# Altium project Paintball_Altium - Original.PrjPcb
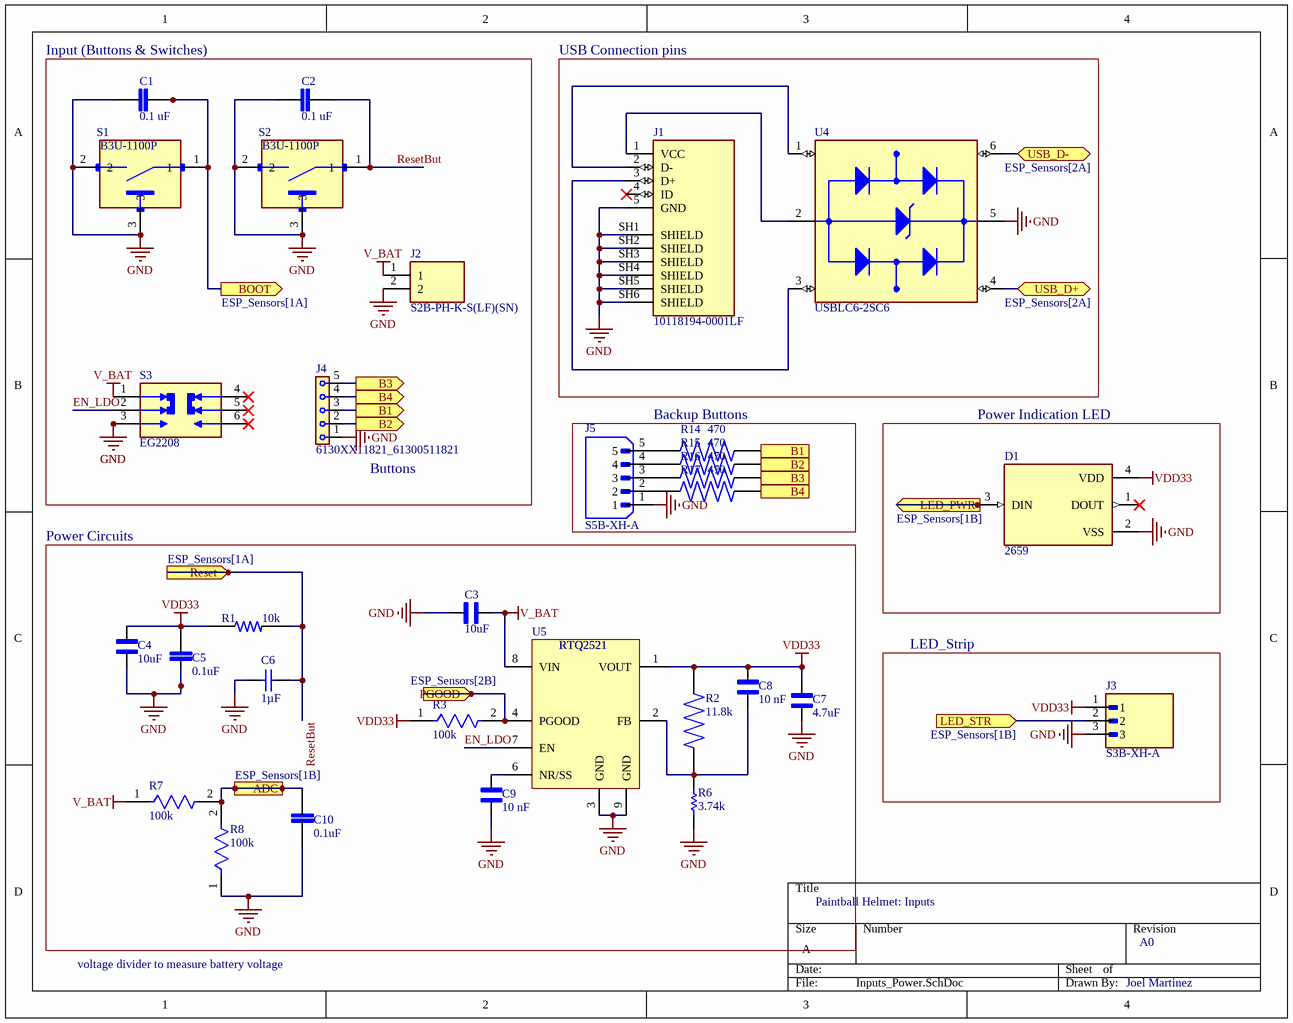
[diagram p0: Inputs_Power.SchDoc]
2 sheets, 55 parts. Net scope: flat (ports and power ports of the same name join across sheets).
Board files: Paintball_PCB_copy.PcbDoc, Paintball_PCB.PcbDoc
Sheets:
  Inputs_Power.SchDoc
  ESP_Sensors.SchDoc

## Sheet Inputs_Power.SchDoc
size A; SheetNumber: 1; SheetTotal: 2

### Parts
C1  0.1 uF  [CAPC1608X90]
C2  0.1 uF  [CAPC1608X90]
C3  10uF  [CAPC1608X90N]
C4  10uF  [CAPC1608X90N]
C5  0.1uF  [CAPC1608X90]
C6  1µF  [CAPC1608X90X35LL15T15]
C7  4.7uF  [CAPC1608X95N]
C8  10 nF  [CAPC1608X90N]
C9  10 nF  [CAPC1608X90N]
C10  0.1uF  [CAPC1608X90]
D1  2659  [2659]
J1  10118194-0001LF  [AMPHENOL_10118194-0001LF]
J2  S2B-PH-K-S(LF)(SN)  [JST_S2B-PH-K-S(LF)(SN)]
J3  S3B-XH-A  [JST_S3B-XH-A]
J4  6130XX11821_61300511821  [61300511821]
J5  S5B-XH-A  [JST_S5B-XH-A]
R1  10k  [RESC1607X60N]
R2  11.8k  [RESC1508X55N]
R3  100k  [FP-RC0603-0_55-MFG]
R6  3.74k  [RESC1609X50X30LL10T20]
R7  100k  [FP-RC0603-0_55-MFG]
R8  100k  [FP-RC0603-0_55-MFG]
R14  470  [RESC1608X55N]
R15  470  [RESC1608X55N]
R16  470  [RESC1608X55N]
R17  470  [RESC1608X55N]
S1  B3U-1100P  [SW_B3U-1100P]
S2  B3U-1100P  [SW_B3U-1100P]
S3  EG2208  [SW_EG2208]
U4  USBLC6-2SC6  [SOT95P280X145-6N]
U5  RTQ2521  [RTQ2521]

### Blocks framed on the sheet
USB Connection pins: J1 U4
Backup Buttons: J5 R14-R17
Power Indication LED: D1
Power Circuits: C3-C10 R1-R3 R6-R8 U5
LED_Strip: J3

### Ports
ADC (in, see ESP_Sensors[1B]), B1 (out, see ESP_Sensors[1A], Inputs_Power[2B]), B1 (out, see ESP_Sensors[1A], Inputs_Power[3B]), B2 (out, see ESP_Sensors[1A], Inputs_Power[2B]), B2 (out, see ESP_Sensors[1A], Inputs_Power[3B]), B3 (out, see ESP_Sensors[1A], Inputs_Power[2B]), B3 (out, see ESP_Sensors[1A], Inputs_Power[3B]), B4 (out, see ESP_Sensors[1A], Inputs_Power[2B]), B4 (out, see ESP_Sensors[1A], Inputs_Power[3B]), BOOT (out, see ESP_Sensors[1A]), LED_PWR (in, see ESP_Sensors[1B]), LED_STR (in, see ESP_Sensors[1B]), PGOOD (out, see ESP_Sensors[2B]), Reset (out, see ESP_Sensors[1A]), USB_D+ (bidir, see ESP_Sensors[2A]), USB_D- (bidir, see ESP_Sensors[2A])

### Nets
GND: C1.1 C2.1 C3.1 C4.1 C5.1 C6.1 C7.1 C9.1 C10.1 D1.2(VSS) J1.5(GND) J1.SH1(SHIELD) J1.SH2(SHIELD) J1.SH3(SHIELD) J1.SH4(SHIELD) J1.SH5(SHIELD) J1.SH6(SHIELD) J2.2 J3.3 J4.1 J5.1 R6.1 R8.1 S1.2 S1.3 S2.2 S2.3 S3.3 U4.5(VBUS) U5.3(GND) U5.9(GND)
V_BAT: C3.2 J2.1 R7.1 S3.1 U5.8(VIN)
VDD33: C4.2 C5.2 C7.2 C8.2 D1.4(VDD) J3.1 R1.1 R2.2 R3.1 U5.1(VOUT)
B1: J4.3 R14.2 ; port B1
B2: J4.2 R15.2 ; port B2
B3: J4.5 R16.2 ; port B3
B4: J4.4 R17.2 ; port B4
EN_LDO: S3.2 U5.7(EN)
ResetBut: C2.2 C6.2 R1.2 S2.1 ; port Reset  [project net Reset]
NetC1_2: C1.2 S1.1 ; port BOOT
NetC8_1: C8.1 R2.1 R6.2 U5.2(FB)
NetC9_2: C9.2 U5.6(NR/SS)
NetC10_2: C10.2 R7.2 R8.2 ; port ADC
NetD1_3: D1.3(DIN) ; port LED_PWR
NetJ1_1: J1.1(VCC) U4.2(GND)
NetJ1_2: J1.2(D-) U4.1(I/O1_IN)
NetJ1_3: J1.3(D+) U4.3(I/O2_IN)
NetJ3_2: J3.2 ; port LED_STR
NetJ5_2: J5.2 R17.1
NetJ5_3: J5.3 R16.1
NetJ5_4: J5.4 R15.1
NetJ5_5: J5.5 R14.1
NetR3_2: R3.2 U5.4(PGOOD) ; port PGOOD
NetU4_4: U4.4(I/O2_OUT) ; port USB_D+
NetU4_6: U4.6(I/O1_OUT) ; port USB_D-

Not connected (* = marked no-connect by the designer): D1 1(DOUT)*; J1 4(ID)*; S3 4* 5* 6*

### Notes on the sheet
- (near C1) Input (Buttons & Switches)
- (near J4) Buttons
- Paintball Helmet: Inputs
- voltage divider to measure battery voltage
- A0
- Joel Martinez

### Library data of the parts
C1 C2 C5 C10 = C0603C104K5RACTU: 0.1 ÂµF Â±10% 50V Ceramic Capacitor X7R 0603 (1608 Metric); MF: KEMET
C3 C4 = CL10A106KP8NNNC: 10 ÂµF Â±10% 10V Ceramic Capacitor X5R 0603 (1608 Metric); MF: Samsung
C6 = CMP-2006-02241-1: Part Number: C0603C105K9PACTU; Manufacturer: Kemet
C7 = CL10B475KQ8NQNC: 4.7 ÂµF Â±10% 6.3V Ceramic Capacitor X7R 0603 (1608 Metric); MF: Samsung Electro-Mechanics
C8 C9 = C0603C103K5RACTU: 10000 pF ±10% 50V Ceramic Capacitor X7R 0603 (1608 Metric)
D1 = 2659: 20 AWG Hook-Up Wire 26/34 White 300V 40.00' _12.19m_; MF: Adafruit Industries
J1 = 10118194-0001LF: Micro USB, Input Output Connectors, B TYPE RECEPTACLE with flange; MF: Amphenol ICC
J2 = S2B-PH-K-S(LF)(SN): Connector Header Through Hole, Right Angle 2 position; MF: JST Sales America Inc.
J4 = 6130XX11821_61300511821: 5 Position Receptacle Connector 0.100 (2.54mm) Through Hole Gold; MF: WÃ¼rth Elektronik
J5 = S5B-XH-A: Connector Header Through Hole, Right Angle 5 position 0.098 (2.50mm); MF: JST Sales
R1 = RC0603FR-0710KL: 10 kOhms Â±1% 0.1W, 1/10W Chip Resistor 0603 (1608 Metric) Moisture Resistant Thick Film; MF: Yageo
R2 = RMCF0603FT11K8: 11.8 kOhms Â±1% 0.1W, 1/10W Chip Resistor 0603 (1608 Metric) Automotive AEC-Q200 Thick Film; MF: Stackpole Electronics Inc
R3 R7 R8 = CMP-2100-03662-2: RES SMD 100K OHM 1% 1/10W 0603; Voltage Rating (DC): 50V; Resistance: 100kR; Max Power Dissipation: 100mW; Temperature Coefficient: 100ppm/°C; Working Voltage: 75V
R6 = CMP-2000-03309-1: 3.74 kOhms ±1% 0.125W, 1/8W Chip Resistor 0603 (1608 Metric) Automotive AEC-Q200 Thick Film; Part Number: CRCW06033K74FKEA; Manufacturer: Vishay Dale
R14-R17 = RC0603JR-07470RL: 470 Ohms Â±5% 0.1W, 1/10W Chip Resistor 0603 (1608 Metric) Moisture Resistant Thick Film; MF: Yageo
S1 S2 = B3U-1100P: Tactile Switch SPST-NO Top Actuated Surface Mount; MF: Omron
S3 = EG2208: 2P2T Sub-miniature Slide Switch; MF: E-Switch
U4 = USBLC6-2SC6: 17V Clamp 5A (8/20Âµs) Ipp Tvs Diode Surface Mount SOT-23-6; MF: STMicroelectronics

## Sheet ESP_Sensors.SchDoc
size B; SheetNumber: 2; SheetTotal: 2
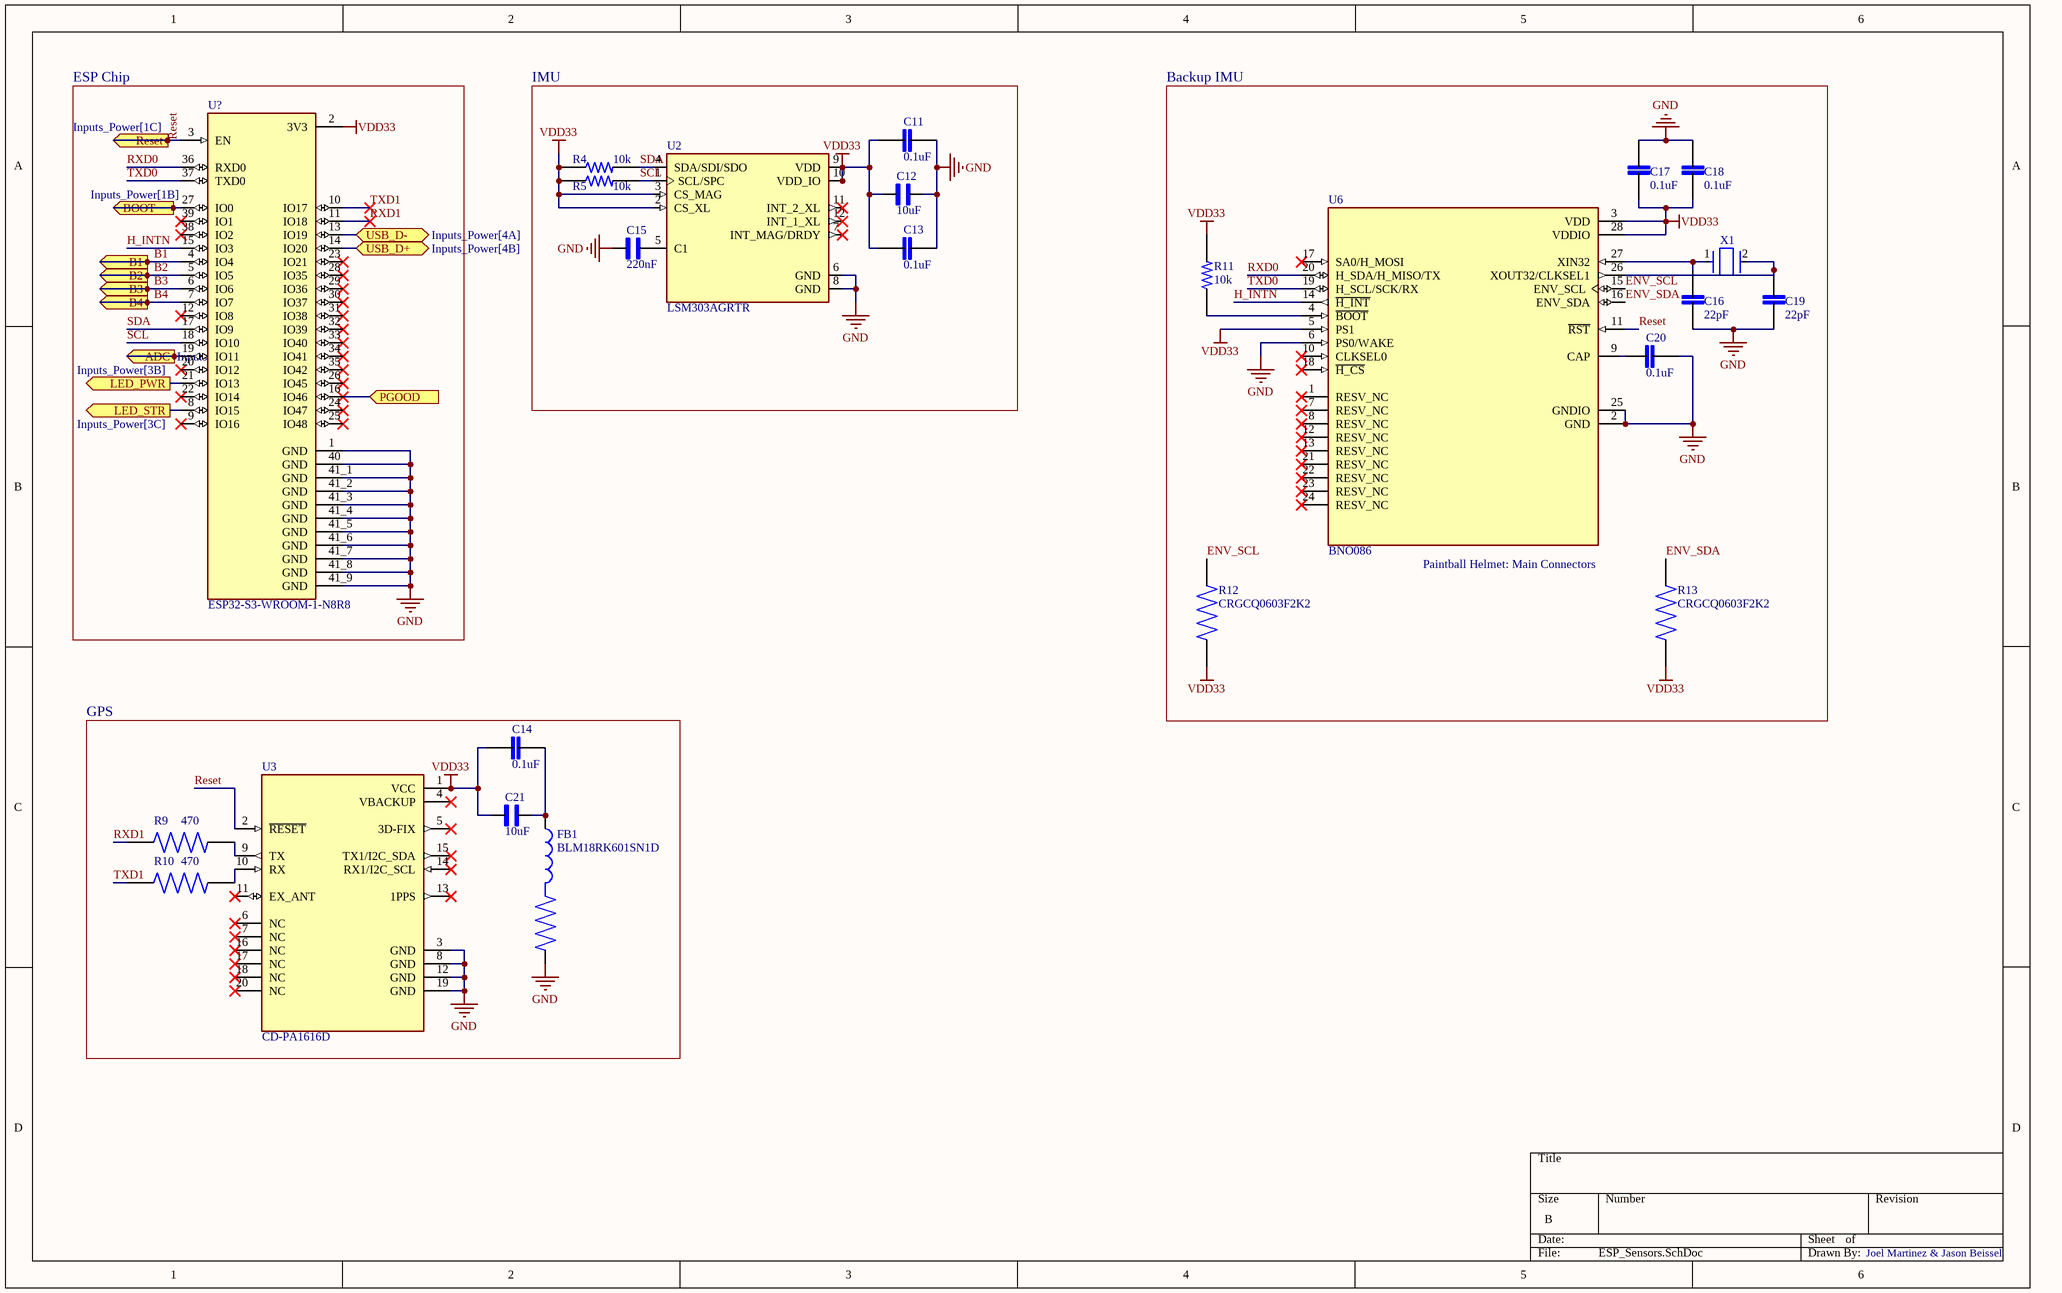
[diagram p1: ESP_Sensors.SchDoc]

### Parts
C11  0.1uF  [CAPC1608X90]
C12  10uF  [CAPC1608X90N]
C13  0.1uF  [CAPC1608X90]
C14  0.1uF  [CAPC1608X90]
C15  220nF  [CAPC1608X90N]
C16  22pF  [CAPC1608X90]
C17  0.1uF  [CAPC1608X90]
C18  0.1uF  [CAPC1608X90]
C19  22pF  [CAPC1608X90]
C20  0.1uF  [CAPC1608X90]
C21  10uF  [CAPC1608X90N]
FB1  BLM18RK601SN1D  [BEADC1608X95N]
R4  10k  [RESC1607X60N]
R5  10k  [RESC1607X60N]
R9  470  [RESC1608X55N]
R10  470  [RESC1608X55N]
R11  10k  [RESC1607X60N]
R12  CRGCQ0603F2K2  [RESC1608X55N]
R13  CRGCQ0603F2K2  [RESC1608X55N]
U2  LSM303AGRTR  [LGA12R50P_200X200X100]
U3  CD-PA1616D  [XCVR_CD-PA1616D]
U6  BNO086  [IC_BNO086]
U?  ESP32-S3-WROOM-1-N8R8  [XCVR_ESP32S3WROOM1N8R8]
X1  ABS07-32.768KHZ-T  [FP-ABS07-MFG]  (value not drawn)

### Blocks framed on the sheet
ESP Chip: U?
IMU: C11-C13 C15 R4 R5 U2
Backup IMU: C16-C20 R11-R13 U6 X1
GPS: C14 C21 FB1 R9 R10 U3

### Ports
ADC (in, see Inputs_Power[1D]), B1 (in, see Inputs_Power[2B], Inputs_Power[3B]), B2 (in, see Inputs_Power[2B], Inputs_Power[3B]), B3 (in, see Inputs_Power[2B], Inputs_Power[3B]), B4 (in, see Inputs_Power[2B], Inputs_Power[3B]), BOOT (in, see Inputs_Power[1B]), LED_PWR (out, see Inputs_Power[3B]), LED_STR (out, see Inputs_Power[3C]), PGOOD (in, see Inputs_Power[2C]), Reset (in, see Inputs_Power[1C]), USB_D+ (bidir, see Inputs_Power[4B]), USB_D- (bidir, see Inputs_Power[4A])

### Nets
GND: C11.2 C12.2 C13.2 C15.1 C16.1 C17.2 C18.2 C19.1 C20.2 FB1.2 U2.6(GND) U2.8(GND) U3.3(GND) U3.8(GND) U3.12(GND) U3.19(GND) U6.2(GND) U6.6(PS0/WAKE) U6.25(GNDIO) U?.1(GND) U?.40(GND) U?.41_1(GND) U?.41_2(GND) U?.41_3(GND) U?.41_4(GND) U?.41_5(GND) U?.41_6(GND) U?.41_7(GND) U?.41_8(GND) U?.41_9(GND)
VDD33: C11.1 C12.1 C13.1 C14.1 C17.1 C18.1 C21.1 R4.1 R5.1 R11.2 R12.1 R13.1 U2.2(CS_XL) U2.3(CS_MAG) U2.9(VDD) U2.10(VDD_IO) U3.1(VCC) U6.3(VDD) U6.5(PS1) U6.28(VDDIO) U?.2(3V3)
B1: U?.4(IO4) ; port B1
B2: U?.5(IO5) ; port B2
B3: U?.6(IO6) ; port B3
B4: U?.7(IO7) ; port B4
ENV_SCL: R12.2 U6.15(ENV_SCL)
ENV_SDA: R13.2 U6.16(ENV_SDA)
H_INTN: U6.14(~{H_INT}) U?.15(IO3)
Reset: U3.2(~{RESET}) U6.11(~{RST}) U?.3(EN) ; port Reset
RXD0: U6.20(H_SDA/H_MISO/TX) U?.36(RXD0)
RXD1: R9.1 U?.11(IO18)
SCL: R5.2 U2.1(SCL/SPC) U?.18(IO10)
SDA: R4.2 U2.4(SDA/SDI/SDO) U?.17(IO9)
TXD0: U6.19(H_SCL/SCK/RX) U?.37(TXD0)
TXD1: R10.1 U?.10(IO17)
NetC1_2: U?.27(IO0) ; port BOOT
NetC10_2: U?.19(IO11) ; port ADC
NetC14_2: C14.2 C21.2 FB1.1
NetC15_2: C15.2 U2.5(C1)
NetC16_2: C16.2 U6.27(XIN32) X1.1
NetC19_2: C19.2 U6.26(XOUT32/CLKSEL1) X1.2
NetC20_1: C20.1 U6.9(CAP)
NetD1_3: U?.21(IO13) ; port LED_PWR
NetJ3_2: U?.8(IO15) ; port LED_STR
NetR3_2: U?.16(IO46) ; port PGOOD
NetR9_2: R9.2 U3.9(TX)
NetR10_2: R10.2 U3.10(RX)
NetR11_1: R11.1 U6.4(~{BOOT})
NetU4_4: U?.14(IO20) ; port USB_D+
NetU4_6: U?.13(IO19) ; port USB_D-

Not connected (* = marked no-connect by the designer): U2 7(INT_MAG/DRDY)* 11(INT_2_XL)* 12(INT_1_XL)*; U3 4(VBACKUP)* 5(3D-FIX)* 6(NC)* 7(NC)* 11(EX_ANT)* 13(1PPS)* 14(RX1/I2C_SCL)* 15(TX1/I2C_SDA)* 16(NC)* 17(NC)* 18(NC)* 20(NC)*; U6 1(RESV_NC)* 7(RESV_NC)* 8(RESV_NC)* 10(CLKSEL0)* 12(RESV_NC)* 13(RESV_NC)* 17(SA0/H_MOSI)* 18(~{H_CS})* 21(RESV_NC)* 22(RESV_NC)* 23(RESV_NC)* 24(RESV_NC)*; U? 9(IO16)* 12(IO8)* 20(IO12)* 22(IO14)* 23(IO21)* 24(IO47)* 25(IO48)* 26(IO45)* 28(IO35)* 29(IO36)* 30(IO37)* 31(IO38)* 32(IO39)* 33(IO40)* 34(IO41)* 35(IO42)* 38(IO2)* 39(IO1)*

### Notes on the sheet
- Paintball Helmet: Main Connectors
- Joel Martinez & Jason Beissel

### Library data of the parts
C11 C13 C14 C17 C18 C20 = C0603C104K5RACTU: as C1 on sheet Inputs_Power
C12 C21 = CL10A106KP8NNNC: as C3 on sheet Inputs_Power
C15 = GCM188R71H224KA64D: Multilayer Ceramic Capacitor, AEC-Q200 GCM Series, 0.22 - F, - 10%, X7R, 50 V; MF: Murata Electronics
C16 C19 = C0603C220J5GACTU: 22pF Â±5% 50V Ceramic Capacitor C0G, NP0 0603 (1608 Metric); MF: KEMET
FB1 = BLM18RK601SN1D: FERRITE BEAD 600 OHM 0603 1LN
R4 R5 R11 = RC0603FR-0710KL: as R1 on sheet Inputs_Power
R9 R10 = RC0603JR-07470RL: as R14 on sheet Inputs_Power
R12 R13 = CRGCQ0603F2K2: Fixed Resistor CRGCQ 0603 2K2 1%; MF: TE Connectivity
U2 = LSM303AGRTR: Accelerometer, Magnetometer, Temperature, 6 Axis Sensor IÂ²C, SPI Output; MF: STMicroelectronics
U3 = CD-PA1616D: CD-PA1616DGNSS patch antenna module; MF: CD Top
U6 = BNO086: Accelerometer, Gyroscope, Magnetometer, Temperature, 9 Axis Sensor I2C, SPI Output; MF: CEVA Technologies, Inc.
U? = ESP32-S3-WROOM-1-N8R8: Bluetooth, WiFi 802.11b/g/n, Bluetooth v5.0 Transceiver Module 2.4GHz PCB Trace Surface Mount; MF: Espressif Systems
X1 = CMP-0447-00001-4: Crystal 32.768kHz ±20ppm (Tol) 12.5pF FUND 70kΩ 2-Pin CSMD T/R; ESR (Equivalent Series Resistance): 70kR

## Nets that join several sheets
GND: Inputs_Power (31 pins), ESP_Sensors (30 pins)
VDD33: Inputs_Power (10 pins), ESP_Sensors (21 pins)
B1: Inputs_Power (J4.3 R14.2), ESP_Sensors (U?.4)
B2: Inputs_Power (J4.2 R15.2), ESP_Sensors (U?.5)
B3: Inputs_Power (J4.5 R16.2), ESP_Sensors (U?.6)
B4: Inputs_Power (J4.4 R17.2), ESP_Sensors (U?.7)
NetC1_2: Inputs_Power (C1.2 S1.1), ESP_Sensors (U?.27)
NetC10_2: Inputs_Power (C10.2 R7.2 R8.2), ESP_Sensors (U?.19)
NetD1_3: Inputs_Power (D1.3), ESP_Sensors (U?.21)
NetJ3_2: Inputs_Power (J3.2), ESP_Sensors (U?.8)
NetR3_2: Inputs_Power (R3.2 U5.4), ESP_Sensors (U?.16)
NetU4_4: Inputs_Power (U4.4), ESP_Sensors (U?.14)
NetU4_6: Inputs_Power (U4.6), ESP_Sensors (U?.13)
Reset: Inputs_Power (C2.2 C6.2 R1.2 S2.1), ESP_Sensors (U3.2 U6.11 U?.3)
